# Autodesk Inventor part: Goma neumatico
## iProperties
Created: 2008-01
Part Number: Goma neumatico
Document SubType Name: Modeling
Designer: eruiz-tagle
Mass: 3.11045 g
Surface Area: 25.0832 cm^2
Volume: 3.11045 cm^3
Density: 1 g/cm^3
Author: eruiz-tagle
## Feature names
1. Revolution1
2. Fillet1
3. Extrusion2
4. Extrusion3
5. Fillet2
6. Circular Pattern1
